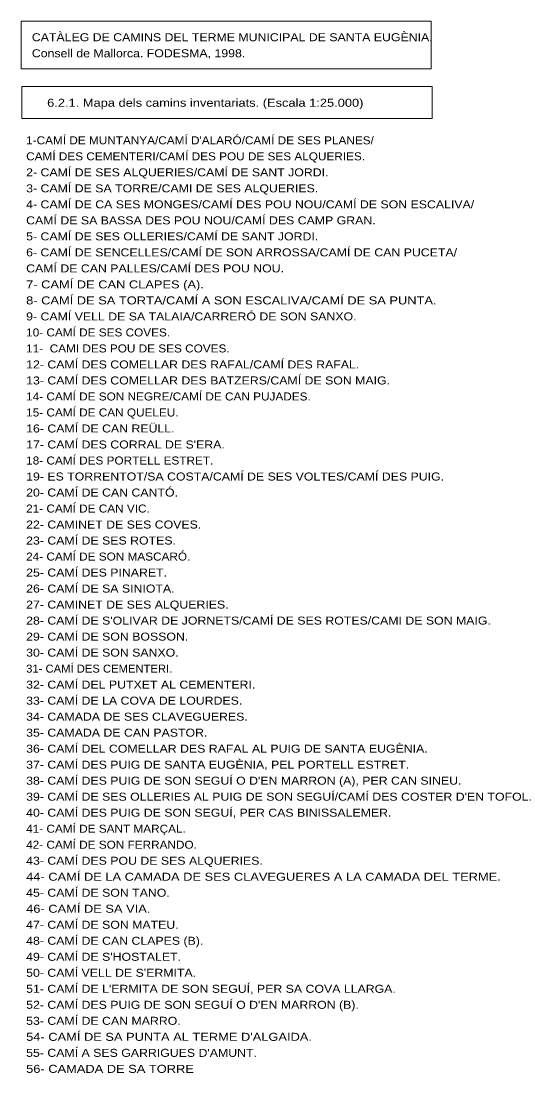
# Model space of a CAD drawing. Extents: x 476989 to 498418, y 4381813 to 4416555.
# Drawn here: x 480312 to 483391, y 4382347 to 4388918 of the extents above; entities that cross this region are included whole.
import ezdxf
from ezdxf.enums import TextEntityAlignment as Align

# ---------------------------------------------------------------- set-up
doc = ezdxf.new("R2010")
doc.units = 0
doc.header["$LTSCALE"] = 20
doc.layers.add('13', color=7, linetype='Continuous', lineweight=13)

msp = doc.modelspace()

# ---------------------------------------------------------------- linework, layer by layer
at = {"layer": '13'}
for points in [[(480311.63, 4388917.52), (482873.59, 4388917.52), (482873.59, 4388618.76), (480311.63, 4388618.76)], [(480316.85, 4388508.69), (482878.81, 4388508.69), (482878.81, 4388309.52), (480316.85, 4388309.52)]]:
    msp.add_lwpolyline(points, close=True, dxfattribs=at)

# ---------------------------------------------------------------- texts
for s, width, p in [('CATÀLEG DE CAMINS DEL TERME MUNICIPAL DE SANTA EUGÈNIA.', 1.15, (480379.02, 4388791.28)), ('Consell de Mallorca. FODESMA, 1998.', 1.15, (480379.02, 4388691.28)), ("1-CAMÍ DE MUNTANYA/CAMÍ D'ALARÓ/CAMÍ DE SES PLANES/", 1.1, (480343.57, 4388147.39)), ('CAMÍ DES CEMENTERI/CAMÍ DES POU DE SES ALQUERIES.', 1.1, (480343.57, 4388047.39)), ('2- CAMÍ DE SES ALQUERIES/CAMÍ DE SANT JORDI.', 1.15, (480343.57, 4387947.39)), ('3- CAMÍ DE SA TORRE/CAMI DE SES ALQUERIES.', 1.15, (480343.57, 4387847.39)), ('4- CAMÍ DE CA SES MONGES/CAMÍ DES POU NOU/CAMÍ DE SON ESCALIVA/', 1.15, (480343.57, 4387747.39)), ('CAMÍ DE SA BASSA DES POU NOU/CAMÍ DES CAMP GRAN.', 1.15, (480343.57, 4387647.39)), ('5- CAMÍ DE SES OLLERIES/CAMÍ DE SANT JORDI.', 1.15, (480343.57, 4387547.39)), ('6- CAMÍ DE SENCELLES/CAMÍ DE SON ARROSSA/CAMÍ DE CAN PUCETA/', 1.15, (480343.57, 4387447.39)), ('CAMÍ DE CAN PALLES/CAMÍ DES POU NOU.', 1.15, (480343.57, 4387347.39)), ('7- CAMÍ DE CAN CLAPES (A).', 1.2, (480343.57, 4387247.39)), ('8- CAMÍ DE SA TORTA/CAMÍ A SON ESCALIVA/CAMÍ DE SA PUNTA.', 1.2, (480343.57, 4387147.39)), ('9- CAMÍ VELL DE SA TALAIA/CARRERÓ DE SON SANXO.', 1.15, (480343.57, 4387047.39)), ('10- CAMÍ DE SES COVES.', 1.1, (480343.57, 4386947.39)), ('11-  CAMI DES POU DE SES COVES.', 1.1, (480343.57, 4386847.39)), ('12- CAMÍ DES COMELLAR DES RAFAL/CAMÍ DES RAFAL.', 1.15, (480343.57, 4386747.39)), ('13- CAMÍ DES COMELLAR DES BATZERS/CAMÍ DE SON MAIG.', 1.15, (480343.57, 4386647.39)), ('14- CAMÍ DE SON NEGRE/CAMÍ DE CAN PUJADES.', 1.1, (480343.57, 4386547.39)), ('15- CAMÍ DE CAN QUELEU.', 1.1, (480343.57, 4386447.39)), ('16- CAMÍ DE CAN REÜLL.', 1.15, (480343.57, 4386347.39)), ("17- CAMÍ DES CORRAL DE S'ERA.", 1.15, (480343.57, 4386247.39)), ('18- CAMÍ DES PORTELL ESTRET.', 1.1, (480343.57, 4386147.39)), ('19- ES TORRENTOT/SA COSTA/CAMÍ DE SES VOLTES/CAMÍ DES PUIG.', 1.15, (480343.57, 4386047.39)), ('20- CAMÍ DE CAN CANTÓ.', 1.15, (480343.57, 4385947.39)), ('21- CAMÍ DE CAN VIC.', 1.1, (480343.57, 4385847.39)), ('22- CAMINET DE SES COVES.', 1.15, (480343.57, 4385747.39)), ('23- CAMÍ DE SES ROTES.', 1.15, (480343.57, 4385647.39)), ('24- CAMÍ DE SON MASCARÓ.', 1.1, (480343.57, 4385547.39)), ('25- CAMÍ DES PINARET.', 1.15, (480343.57, 4385447.39)), ('26- CAMÍ DE SA SINIOTA.', 1.15, (480343.57, 4385347.39)), ('27- CAMINET DE SES ALQUERIES.', 1.15, (480343.57, 4385247.39)), ("28- CAMÍ DE S'OLIVAR DE JORNETS/CAMÍ DE SES ROTES/CAMI DE SON MAIG.", 1.15, (480343.57, 4385147.39)), ('29- CAMÍ DE SON BOSSON.', 1.15, (480343.57, 4385047.39)), ('30- CAMÍ DE SON SANXO.', 1.15, (480343.57, 4384947.39)), ('31- CAMÍ DES CEMENTERI.', 1.05, (480343.57, 4384847.39)), ('32- CAMÍ DEL PUTXET AL CEMENTERI.', 1.15, (480343.57, 4384747.39)), ('33- CAMÍ DE LA COVA DE LOURDES.', 1.15, (480343.57, 4384647.39)), ('34- CAMADA DE SES CLAVEGUERES.', 1.15, (480343.57, 4384547.39)), ('35- CAMADA DE CAN PASTOR.', 1.15, (480343.57, 4384447.39)), ('36- CAMÍ DEL COMELLAR DES RAFAL AL PUIG DE SANTA EUGÈNIA.', 1.15, (480343.57, 4384347.39)), ('37- CAMÍ DES PUIG DE SANTA EUGÈNIA, PEL PORTELL ESTRET.', 1.15, (480343.57, 4384247.39)), ("38- CAMÍ DES PUIG DE SON SEGUÍ O D'EN MARRON (A), PER CAN SINEU.", 1.15, (480343.57, 4384147.39)), ("39- CAMÍ DE SES OLLERIES AL PUIG DE SON SEGUÍ/CAMÍ DES COSTER D'EN TOFOL.", 1.15, (480343.57, 4384047.39)), ('40- CAMÍ DES PUIG DE SON SEGUÍ, PER CAS BINISSALEMER.', 1.15, (480343.57, 4383947.39)), ('41- CAMÍ DE SANT MARÇAL.', 1.1, (480343.57, 4383847.39)), ('42- CAMÍ DE SON FERRANDO.', 1.1, (480343.57, 4383747.39)), ('43- CAMÍ DES POU DE SES ALQUERIES.', 1.15, (480343.57, 4383647.39)), ('44- CAMÍ DE LA CAMADA DE SES CLAVEGUERES A LA CAMADA DEL TERME.', 1.2, (480343.57, 4383547.39)), ('45- CAMÍ DE SON TANO.', 1.15, (480343.57, 4383447.39)), ('46- CAMÍ DE SA VIA.', 1.2, (480343.57, 4383347.39)), ('47- CAMÍ DE SON MATEU.', 1.15, (480343.57, 4383247.39)), ('48- CAMÍ DE CAN CLAPES (B).', 1.15, (480343.57, 4383147.39)), ("49- CAMÍ DE S'HOSTALET.", 1.15, (480343.57, 4383047.39)), ("50- CAMÍ VELL DE S'ERMITA.", 1.15, (480343.57, 4382947.39)), ("51- CAMÍ DE L'ERMITA DE SON SEGUÍ, PER SA COVA LLARGA.", 1.15, (480343.57, 4382847.39)), ("52- CAMÍ DES PUIG DE SON SEGUÍ O D'EN MARRON (B).", 1.15, (480343.57, 4382747.39)), ('53- CAMÍ DE CAN MARRO.', 1.15, (480343.57, 4382647.39)), ("54- CAMÍ DE SA PUNTA AL TERME D'ALGAIDA.", 1.2, (480343.57, 4382547.39)), ("55- CAMÍ A SES GARRIGUES D'AMUNT.", 1.15, (480343.57, 4382447.39)), ('56- CAMADA DE SA TORRE', 1.2, (480343.57, 4382347.39))]:
    msp.add_text(s, height=50, dxfattribs=dict(at, width=width)).set_placement(p)
at = {"layer": '13', "width": 1.2}
msp.add_text('6.2.1. Mapa dels camins inventariats. (Escala 1:25.000)', height=50, dxfattribs=at).set_placement((481462.52, 4388382.09), align=Align.CENTER)

doc.saveas('drawing.dxf')
